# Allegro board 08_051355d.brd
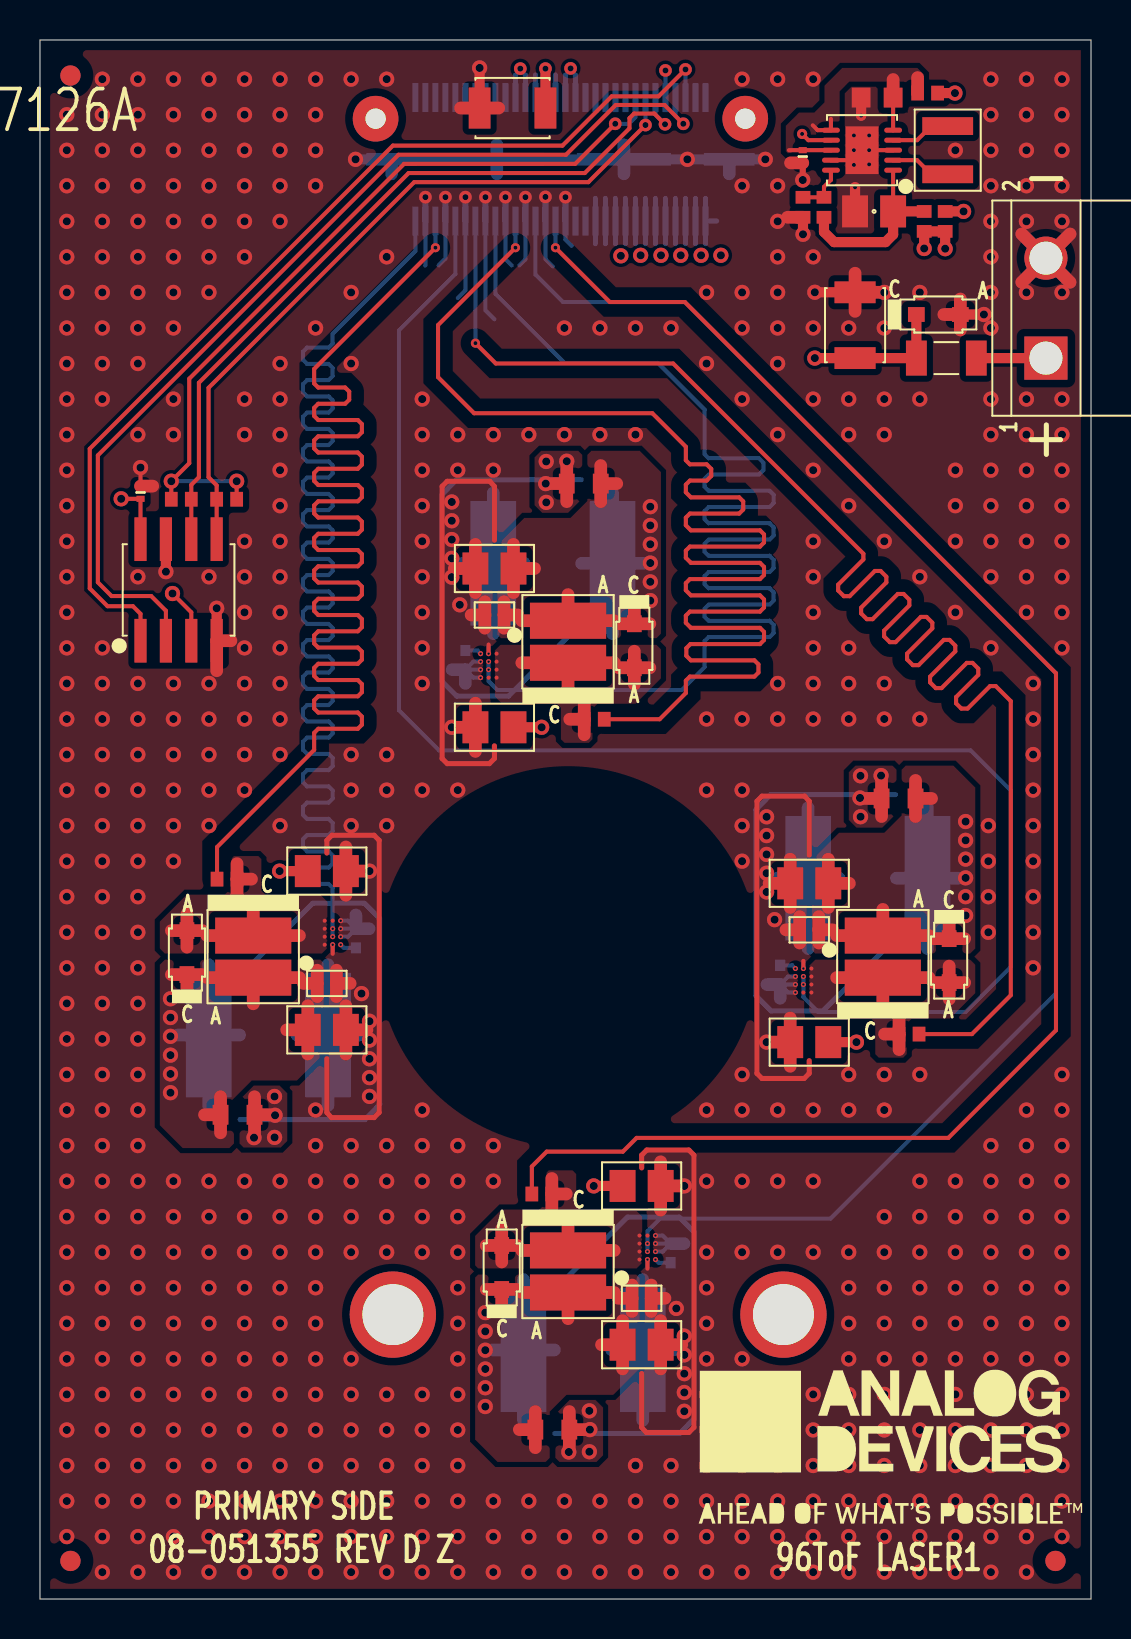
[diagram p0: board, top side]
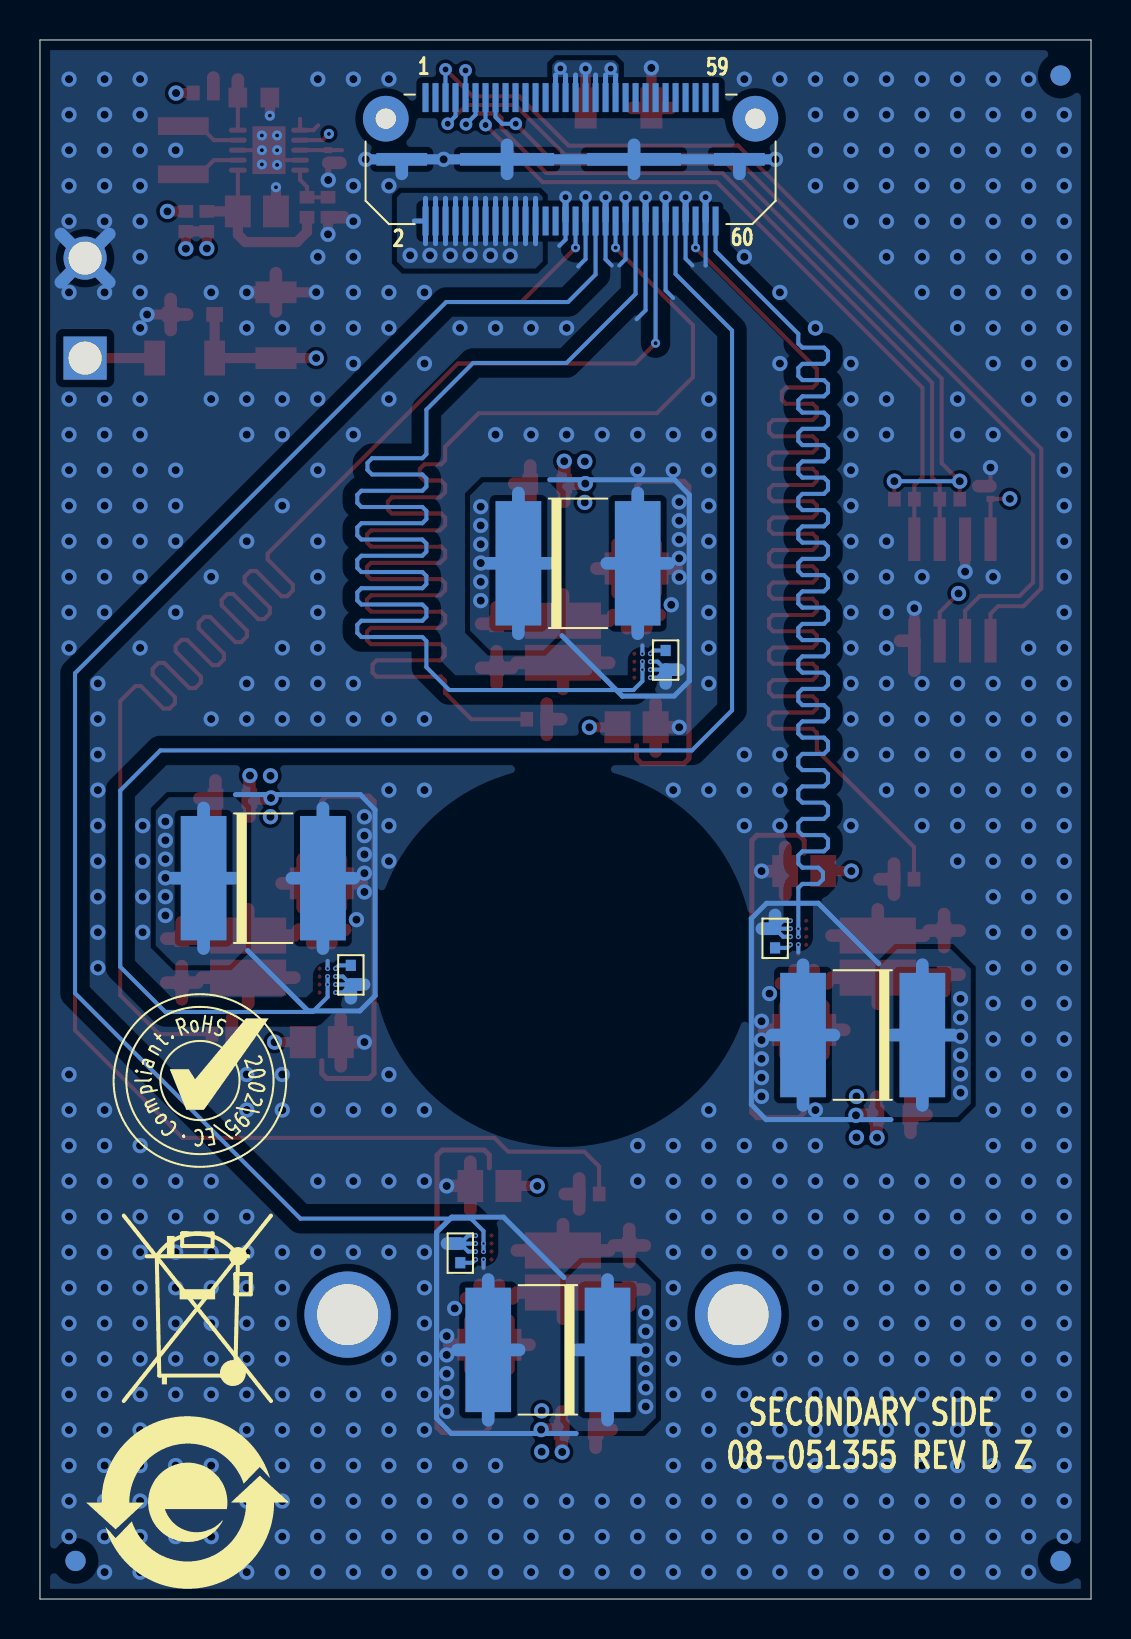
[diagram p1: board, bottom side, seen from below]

Outline 52.58 x 77.98 mm; copper layers: TOP, L2_GND, L3_PWR, L4_PWR, L5_GND, BOTTOM. Coordinates in mm from the lower left corner of the outline.
Outline path: 0,77.98 52.58,77.98 52.58,0 0,0 0,77.98

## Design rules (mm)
constraint set DEFAULT: min track width 0.102
net group TAL: nets TAL1 TAL2 TAL3 TAL4

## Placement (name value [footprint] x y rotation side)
C1  0.1uF  [C0402H22]  15.8 33.05 90 bottom
C2  0.1uF  [C0402H22]  31.55 17.3 90 bottom
C3  4.7UF  [C0805H53]  14.35 36.41 0 top
C4  4.7UF  [C0805H53]  30.1 20.66 0 top
C5  0.1uF  [C0402H22]  14.35 30.79 0 top
C6  0.1uF  [C0402H22]  38.48 33.47 180 top
C7  0.1uF  [C0402H22]  21.28 46.96 270 bottom
C8  0.1uF  [C0402H22]  37.03 31.21 270 bottom
C9  0.1uF  [C0402H22]  22.73 49.22 180 top
C10  0.1uF  [C0402H22]  30.1 15.04 0 top
C11  4.7UF  [C0805H53]  22.73 43.6 180 top
C12  4.7UF  [C0805H53]  38.48 27.85 180 top
C18  22UF  [C1210H106]  40.77 63.71 270 top
C19  22UF  [C1210H106]  23.64 74.57 0 top
C20  470UF  [C7260]  11.42 28.21 0 bottom
C21  470UF  [C7260]  41.41 36.05 180 bottom
C22  470UF  [C7260]  27.17 12.46 0 bottom
C23  470UF  [C7260]  25.66 51.8 180 bottom
C24  10uF  [C0603]  41.88 75.1 0 top
C25  0.1uF  [C0201]  38.16 72.15 270 top
C26  22UF  [C0805H60]  41.73 69.4 0 top
C27  4.7UF  [C0805H53]  14.35 28.47 0 top
C28  4.7UF  [C0805H53]  38.48 35.8 180 top
C29  4.7UF  [C0805H53]  30.1 12.72 0 top
C30  4.7UF  [C0805H53]  22.73 51.54 180 top
C31  0.1uF  [C0201]  5.03 55.35 270 top
D1  PLZ13B-G3/H  [DO219AC]  7.35 32.33 90 top
D6  PLZ13B-G3/H  [DO219AC]  23.1 16.58 90 top
D8  PLZ13B-G3/H  [DO219AC]  44.94 64.25 0 top
D9  PLZ13B-G3/H  [DO219AC]  29.73 47.68 270 top
D10  PLZ13B-G3/H  [DO219AC]  45.48 31.93 270 top
L1  1.5UH  [L1008_A]  45.41 72.47 270 top
LD1  I940-G2332-NBC-D1-60B45R  [VCSEL2_3_5X3_5]  10.67 32.13 270 top
LD2  I940-G2332-NBC-D1-60B45R  [VCSEL2_3_5X3_5]  42.16 32.13 90 top
LD3  I940-G2332-NBC-D1-60B45R  [VCSEL2_3_5X3_5]  26.42 47.88 90 top
LD4  I940-G2332-NBC-D1-60B45R  [VCSEL2_3_5X3_5]  26.42 16.38 270 top
NOREF  -  []  0 0 0 top
NOREF#2  -  []  206.43 -47.55 0 top
NOREF#3  -  [unnamed#2]  1.52 76.2 0 top
NOREF#4  -  []  201.92 -58.42 0 top
NOREF#5  -  []  10.67 32.13 0 top
NOREF#6  -  []  0 0 0 top
NOREF#7  -  []  26.57 98.68 0 top
NOREF#8  -  [unnamed#2]  37.19 14.22 0 top
NOREF#9  -  []  -170.05 -267.97 0 top
NOREF#10  -  []  26.42 32.13 0 top
NOREF#11  -  []  215.9 215.9 0 top
NOREF#12  -  []  226.11 -117.6 0 top
NOREF#13  -  []  8.51 34.37 0 top
NOREF#14  -  []  52.58 0 90 top
NOREF#15  -  []  0 77.98 0 top
NOREF#16  -  []  26.42 32.13 0 top
NOREF#17  -  []  0 77.98 270 top
NOREF#18  -  []  0 0 0 top
NOREF#19  -  []  19.96 38.24 0 top
NOREF#20  -  []  -34.29 -74.04 0 top
NOREF#21  -  []  -152.4 -254 0 top
NOREF#22  -  [unnamed#2]  50.8 1.91 0 top
NOREF#23  -  []  42.57 7.59 0 top
NOREF#24  -  []  52.58 0 90 top
NOREF#25  -  []  26.42 16.38 90 top
NOREF#26  -  []  119.38 127 0 top
NOREF#27  -  []  0 77.98 0 top
NOREF#28  -  []  1.52 1.91 0 top
NOREF#29  -  []  52.58 0 0 top
NOREF#30  -  []  52.7 77.98 180 top
NOREF#31  -  [unnamed#2]  1.52 1.91 0 top
NOREF#32  -  []  1.52 1.91 0 top
NOREF#33  -  [unnamed#2]  17.65 14.22 0 top
NOREF#34  -  [unnamed#2]  50.8 1.91 180 bottom
NOREF#35  -  [unnamed#2]  1.52 1.91 180 bottom
NOREF#36  -  [unnamed#2]  1.52 76.2 180 bottom
NOREF#37  -  []  35.43 22.86 180 bottom
NOREF#38  -  []  44.58 25.93 180 bottom
NOREF#39  -  []  45.19 4.83 180 bottom
P1  QTH-030-03-L-D-A  [CNSAMTECQTH-030-03-X-D-A]  26.04 72.01 180 bottom
P2  Z5.530.3225.0  [CNWIELAND3225]  50.32 62.07 90 top
R3  50  [R0402]  27.73 44 0 top
R5  0  [R0603]  9.88 24.22 180 top
R6  0  [R0603]  25.63 8.47 180 top
R11  0  [R0603]  27.2 55.79 0 top
R13  0  [R0603]  42.95 40.04 0 top
R22  0  [R1206]  45.34 62.07 0 top
R25  50  [R0402]  9.36 36.01 180 top
R26  50  [R0402]  43.47 28.26 0 top
R29  50  [R0402]  25.11 20.26 180 top
R35  0  [R0402]  38.17 69.61 90 top
R36  0  [R0402]  44.4 75.32 0 top
R37  0  [R0402]  39.22 69.61 270 top
R38  0  [R0402]  45.28 68.9 90 top
R39  0  [R0402]  44.23 68.9 270 top
R40  10K  [R0402]  9.34 55.01 180 top
R41  10K  [R0402]  7.07 55.01 0 top
U1  ADP5202BCBZRL  [WLCSP12H22]  14.64 33.33 0 top
U2  ADP5202BCBZRL  [WLCSP12H22]  38.19 30.94 180 top
U3  ADP5202BCBZRL  [WLCSP12H22]  22.44 46.68 180 top
U4  ADP5202BCBZRL  [WLCSP12H22]  30.39 17.58 0 top
U5  ADP2504ACPZ-5.0  [DFN10_3X3_PAD2_38X1_64]  41.12 72.47 90 top
U6  ADT7410TRZ  [SO8]  6.93 50.47 0 top

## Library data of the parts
C1 C2 C5-C10 = CAP: Tolerance: 10; User Part Number: UPN; alternate symbols: (); part number: CAP_SM-0.1UF,50V,10,E018452,C0402H22; tolerance: 10
C3 C4 C11 C12 C27-C30 = CAP: Tolerance: 10; User Part Number: UPN; alternate symbols: (); part number: CAP_SM-4.7UF,25V,10,E025752,C0805H53; tolerance: 10
C18 C19 = CAP: Tolerance: 10; User Part Number: UPN; alternate symbols: (); part number: CAP_SM-22UF,25V,10,E025745,C1210H106; tolerance: 10
C20-C23 = CAPP: Tolerance: 10; User Part Number: UPN; alternate symbols: (); part number: CAPP_SM-470UF,10V,10,E027243,C7260; tolerance: 10
C24 = CAP: User Part Number: UPN; Tolerance: 20; alternate symbols: (); part number: CAP_SM-10UF,6.3V,20,E007143,C0603; tolerance: 20
C25 C31 = CAP: Tolerance: 20; User Part Number: UPN; alternate symbols: (); part number: CAP_SM-0.1UF,16V,20,E017331,C0201; tolerance: 20
C26 = CAP: Tolerance: 20; User Part Number: UPN; alternate symbols: (); part number: CAP_SM-22UF,10V,20,E032369,C0805H60; tolerance: 20
D1 D6 D8-D10 = DIOZNR: User Part Number: UPN; Tolerance: 2; alternate symbols: (); part number: DIOZNR_SM-PLZ13B-G3/H,13V,2,E025186,DO219AC; tolerance: 2
L1 = IND: Tolerance: 20; User Part Number: UPN; alternate symbols: (); part number: IND_SM-1.5UH,20,E026128,L1008_A; tolerance: 20
LD1-LD4 = DIOLASER: User Part Number: UPN; Tolerance: N/A; alternate symbols: (); part number: DIOLASER_SM-I940-G2332-NBC-D1-110B85R,5V,N/A,E035420,VCSEL2_3_5X3_5; tolerance: N/A
P1 = CN60P_ODD_EVEN_4GND: User Part Number: UPN; Tolerance: N/A; alternate symbols: (); part number: CN60P_ODD_EVEN_4GND_SM-QTH-030-03-L-D-A,E035156,CNSAMTECQTH-030-03-X-D-A; tolerance: N/A
P2 = CN2P: User Part Number: UPN; Tolerance: N/A; alternate symbols: (); part number: CN2P_TH-Z5.530.3225.0,E008161,CNWIELAND3225; tolerance: N/A
R3 R25 R26 R29 = RES: User Part Number: UPN; Tolerance: 0.1; alternate symbols: (R0402L); part number: RES_SM-50,E016309,1/20W,0.1,R0402; tolerance: 0.1
R5 R6 R11 R13 = RES: User Part Number: UPN; Tolerance: 5; alternate symbols: (R0603L); part number: RES_SM-0,E006826,1/10W,5,R0603; tolerance: 5
R22 = RES: User Part Number: UPN; Tolerance: N/A; alternate symbols: (); part number: RES_SM-0,E014206,1/2W,N/A,R1206; tolerance: N/A
R35-R39 = RES: User Part Number: UPN; Tolerance: 5; alternate symbols: (R0402L,R0402L_ALT); part number: RES_SM-0,E003438,N/A,5,R0402; tolerance: 5
R40 R41 = RES: User Part Number: UPN; Tolerance: 5; alternate symbols: (R0402L); part number: RES_SM-10K,E017176,1/10W,5,R0402; tolerance: 5
U1-U4 = ADP5202: Tolerance: N/A; User Part Number: UPN; alternate symbols: (); part number: ADP5202_SM-ADP5202BCBZRL,E034392,WLCSP12H22; tolerance: N/A
U5 = ADP250X: Tolerance: N/A; User Part Number: UPN; alternate symbols: (); part number: ADP250X_SM-ADP2504ACPZ-5.0,E033974,DFN10_3X3_PAD2_38X1_64; tolerance: N/A
U6 = ADT7410: Tolerance: N/A; User Part Number: UPN; alternate symbols: (); part number: ADT7410_SM-ADT7410TRZ,E010871,SO8; tolerance: N/A

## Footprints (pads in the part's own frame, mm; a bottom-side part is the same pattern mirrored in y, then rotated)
C0201
  rect 0.305x0.406 smd: 1(-0.318,0) 2(0.318,0)
C0402H22
  rect 0.559x0.508 smd: 1(-0.479,0) 2(0.479,0)
C0603
  rect 0.94x0.991 smd: 1(-0.8,0) 2(0.8,0)
C0805H53
  rect 1.295x1.6 smd: 1(-0.953,0) 2(0.953,0)
C0805H60
  rect 1.295x1.6 smd: 1(-0.953,0) 2(0.953,0)
C1210H106
  rect 1.092x2.057 smd: 1(-1.646,0) 2(1.646,0)
C7260
  rect 2.286x6.223 smd: N(2.985,0) P(-2.985,0)
CNSAMTECQTH-030-03-X-D-A
  round 2.286 hole 1.016 unplated: (-9.246,2.032) (9.246,2.032)
  rect 0.305x1.448 smd: 1(-7.257,3.086) 2(-7.257,-3.086) 3(-6.756,3.086) 4(-6.756,-3.086) 5(-6.256,3.086) 6(-6.256,-3.086) 7(-5.756,3.086) 8(-5.756,-3.086) 9(-5.255,3.086) 10(-5.255,-3.086) 11(-4.755,3.086) 12(-4.755,-3.086) 13(-4.255,3.086) 14(-4.255,-3.086) 15(-3.754,3.086) 16(-3.754,-3.086) 17(-3.254,3.086) 18(-3.254,-3.086) 19(-2.753,3.086) 20(-2.753,-3.086) 21(-2.253,3.086) 22(-2.253,-3.086) 23(-1.753,3.086) 24(-1.753,-3.086) 25(-1.252,3.086) 26(-1.252,-3.086) 27(-0.752,3.086) 28(-0.752,-3.086) 29(-0.251,3.086) 30(-0.251,-3.086) 31(0.249,3.086) 32(0.249,-3.086) 33(0.749,3.086) 34(0.749,-3.086) 35(1.25,3.086) 36(1.25,-3.086) 37(1.75,3.086) 38(1.75,-3.086) 39(2.25,3.086) 40(2.25,-3.086) 41(2.751,3.086) 42(2.751,-3.086) 43(3.251,3.086) 44(3.251,-3.086) 45(3.752,3.086) 46(3.752,-3.086) 47(4.252,3.086) 48(4.252,-3.086) 49(4.752,3.086) 50(4.752,-3.086) 51(5.253,3.086) 52(5.253,-3.086) 53(5.753,3.086) 54(5.753,-3.086) 55(6.253,3.086) 56(6.253,-3.086) 57(6.754,3.086) 58(6.754,-3.086) 59(7.254,3.086) 60(7.254,-3.086)
  rect 2.54x0.635 smd: PAD1(-8.445,0) PAD4(8.445,0)
  rect 4.699x0.635 smd: PAD2(-3.175,0) PAD3(3.175,0)
CNWIELAND3225
  rect 2.159x2.159 hole 1.651: 1(0,0)
  round 2.159 hole 1.651: 2(5,0)
DFN10_3X3_PAD2_38X1_64
  oval 0.254x0.889 smd: 1(-1,-1.555) 2(-0.5,-1.555) 3(0,-1.555) 4(0.5,-1.555) 5(1,-1.555) 6(1,1.555) 7(0.5,1.555) 8(0,1.555) 9(-0.5,1.555) 10(-1,1.555)
  rect 2.388x1.651 smd: PAD(0,0)
DO219AC
  rect 0.838x0.737 smd: A(1.1,0) C(-1.1,0)
L1008_A
  rect 0.889x2.54 smd: 1(-1.206,0) 2(1.206,0)
R0402
  rect 0.635x0.737 smd: 1(-0.5,0) 2(0.5,0)
R0603
  rect 0.787x0.991 smd: 1(-0.85,0) 2(0.85,0)
R1206
  rect 1.041x1.753 smd: 1(-1.5,0) 2(1.5,0)
SO8
  rect 0.61x2.184 smd: 1(-1.905,-2.54) 2(-0.635,-2.54) 3(0.635,-2.54) 4(1.905,-2.54) 5(1.905,2.54) 6(0.635,2.54) 7(-0.635,2.54) 8(-1.905,2.54)
unnamed#2
  round 1.016 smd: (0,0)
VCSEL2_3_5X3_5
  rect 1.803x3.81 smd: A(1.052,0) C(-1.052,0)
WLCSP12H22
  round 0.203 smd: A1(-0.4,-0.6) A2(-0.4,-0.2) A3(-0.4,0.2) A4(-0.4,0.6) B1(0,-0.6) B2(0,-0.2) B3(0,0.2) B4(0,0.6) C1(0.4,-0.6) C2(0.4,-0.2) C3(0.4,0.2) C4(0.4,0.6)

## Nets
5V_LD: C1.1 C2.1 C3.1 C4.1 C7.1 C8.1 C11.1 C12.1 R38.1 R39.2(N2) U1.C1(VS) U2.C1(VS) U3.C1(VS) U4.C1(VS)
5VDD_CON: C19.2(N2) P1.27 P1.29 P1.31 P1.33 P1.35 P1.37 P1.39 R36.2(N2) R38.2(N2) U5.7
AGND: C1.2(N2) C2.2(N2) C3.2(N2) C4.2(N2) C5.2(N2) C6.2(N2) C7.2(N2) C8.2(N2) C9.2(N2) C10.2(N2) C11.2(N2) C12.2(N2) C18.1 C19.1 C20.N(N2) C21.N(N2) C22.N(N2) C23.N(N2) C24.1 C25.2(N2) C26.1 C27.2(N2) C28.2(N2) C29.2(N2) C30.2(N2) C31.1 D8.A(P) P1.30 P1.34 P1.38 P1.42 P1.46 P1.50 P1.54 P1.58 P1.PAD1 P1.PAD2 P1.PAD3 P1.PAD4 P2.2(N2) R35.1 U1.B1 U1.C2 U1.C3 U1.C4 U2.B1 U2.C2 U2.C3 U2.C4 U3.B1 U3.C2 U3.C3 U3.C4 U4.B1 U4.C2 U4.C3 U4.C4 U5.3 U5.9 U5.PAD U6.4 U6.7
VIN: C24.2(N2) C25.1 R36.1 U5.5 U5.6 U5.8
3P3VDD: C31.2(N2) P1.9 U6.3 U6.8(VDD)
CATHODE1: D1.A(P) LD1.C R25.1 U1.A1 U1.A2 U1.A3 U1.A4
CATHODE2: D10.A(P) LD2.C R26.1 U2.A1 U2.A2 U2.A3 U2.A4
CATHODE3: D9.A(P) LD3.C R3.1 U3.A1 U3.A2 U3.A3 U3.A4
CATHODE4: D6.A(P) LD4.C R29.1 U4.A1 U4.A2 U4.A3 U4.A4
CT_LASER: P1.11 R41.2(N2) U6.6
DS1: C5.1 C20.P C27.1 D1.C LD1.A R5.2(N2)
DS2: C6.1 C21.P C28.1 D10.C LD2.A R13.2(N2)
DS3: C9.1 C23.P C30.1 D9.C LD3.A R11.2(N2)
DS4: C10.1 C22.P C29.1 D6.C LD4.A R6.2(N2)
I2C0_SCL: P1.5 U6.1
I2C0_SDA: P1.7 U6.2
INT_LASER: P1.13 R40.2(N2) U6.5
IOVDD: P1.15 R40.1 R41.1
LD1: P1.60 U1.B2 U1.B3
LD2: P1.52 U2.B2 U2.B3
LD3: P1.44 U3.B2 U3.B3
LD4: P1.36 U4.B2 U4.B3
LD_SUPPLY: P2.1 R5.1 R6.1 R11.1 R13.1 R22.2(N2)
TAL1: P1.56 R25.2(N2)
TAL2: P1.48 R26.2(N2)
TAL3: P1.40 R3.2(N2)
TAL4: P1.32 R29.2(N2)
UNNAMED_4_ADP250X_I213_FB: R35.2(N2) R37.1 U5.10
UNNAMED_4_ADP250X_I213_SW1: L1.1 U5.4
UNNAMED_4_ADP250X_I213_SW2: L1.2(N2) U5.2
VLD_BRD: C18.2(N2) D8.C P1.2 P1.4 P1.6 P1.8 P1.10 P1.12 P1.14 P1.16 P1.18(N9) P1.20 P1.22 P1.24 R22.1
VOUT: C26.2(N2) R37.2(N2) R39.1 U5.1(VOUT)

Pads without a net: P1 1 3 17 19 21 23 25 26 28 41 43 45 47 49 51 53 55 57 59; U1 B4; U2 B4; U3 B4; U4 B4

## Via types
v1: diameter 0.762, hole 0.406, TOP to BOTTOM, 688 vias
v2: diameter 0.635, hole 0.305, TOP to BOTTOM, 17 vias
v3: diameter 0.254, hole 0.127, TOP to BOTTOM, 28 vias
v4: diameter 0.508, hole 0.203, TOP to BOTTOM, 9 vias
v5: diameter 0.457, hole 0.203, TOP to BOTTOM, 4 vias

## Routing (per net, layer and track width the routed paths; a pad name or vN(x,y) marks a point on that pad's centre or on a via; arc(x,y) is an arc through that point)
5V_LD: length 11.8
  TOP w0.508: v1(44.23,67.55) R39.2 R38.1 v1(45.28,67.54) ; C4.1 v1(27.7,20.66) ; C3.1 v1(11.99,36.41) ; C12.1 v1(40.84,27.85) ; C11.1 v1(25.1,43.6)
  BOTTOM w0.203: C1.1 15.2,32.57 v3(15.04,32.73) ; v3(30.79,16.98) 30.95,16.82 C2.1 ; C8.1 37.63,31.69 v3(37.79,31.54) ; C7.1 21.88,47.44 v3(22.04,47.28)
5VDD_CON: length 13.3
  TOP w0.203: v4(38.13,73.28) 38.44,72.97 U5.7
  TOP w0.508: C19.2 v2(25.29,76.55) ; R38.2 v1(46.2,69.4) ; R36.2 v1(45.77,75.32)
  BOTTOM w0.254: P1.35 24.79,76.23 ; P1.33 25.29,76.23 ; 26.54,76.53 v2(26.54,76.56) ; P1.39 23.78,76.23 ; P1.37 24.28,76.23 ; P1.27 26.79,76.23 ; P1.31 25.79,76.23 ; P1.29 26.29,76.23
  vias: v2(24.03,76.55)
AGND: length 206.1
  TOP w0.203: U5.3 v4(41.48,72.47) ; U5.9 40.48,71.97 v4(40.72,71.73) ; v3(22.44,47.28) 22.44,47.74 ; v3(30.39,16.98) 30.39,16.52 ; v3(14.64,32.73) 14.64,32.27 ; C31.1 v1(5.03,56.59) ; v3(38.19,31.54) 38.19,31.92
  TOP w0.305: C25.2 v1(38.16,70.97)
  TOP w0.508: C26.1 v4(40.77,70.61) ; U6.7 v1(6.3,51.38) ; C24.1 v4(41.08,74.2) ; R35.1 v1(38.17,68.26) ; D8.A v1(47.22,64.25) ; C18.1 v1(38.76,65.36) ; C19.1 v1(21.99,76.58) ; U6.4 v1(8.84,49.56)
  TOP w0.635: 40.77,64.41 C18.1 ; C18.1 40.77,66.31 ; C18.1 42.21,65.36 ; C11.2 21.78,44.81 ; C11.2 20.73,43.6 ; C11.2 21.78,42.39 ; 21.78,50.34 C30.2 ; C30.2 20.73,51.54 ; C30.2 21.78,52.75 ; C9.2 22.25,49.88 ; C9.2 21.57,49.22 ; C9.2 22.25,48.56 ; C10.2 30.58,15.7 ; C10.2 30.58,14.38 ; C10.2 31.26,15.04 ; 46.04,63.47 D8.A ; D8.A 45.22,64.25 ; D8.A 46.04,65.02 ; C3.2 16.36,36.41 ; C3.2 15.3,37.62 ; C3.2 15.3,35.2 ; 37.55,71.83 C25.2 ; 36.48,35.8 C28.2 ; C28.2 37.53,37 ; C28.2 37.53,34.59 ; P2.2 51.53,65.86 ; P2.2 49.12,65.86 ; P2.2 51.53,68.27 ; P2.2 49.12,68.27 ; C6.2 38,34.13 ; C6.2 38,32.81 ; C6.2 37.32,33.47 ; 8.84,46.43 U6.4 9.55,47.93 ; C5.2 14.83,31.45 ; C5.2 15.52,30.79 ; C5.2 14.83,30.13 ; C4.2 32.1,20.66 ; C4.2 31.05,21.87 ; C4.2 31.05,19.45 ; C31.1 5.64,55.66 ; C27.2 15.3,29.67 ; C27.2 16.36,28.47 ; C27.2 15.3,27.26 ; 37.53,26.65 C12.2 ; C12.2 37.53,29.06 ; C12.2 36.48,27.85 ; 31.05,11.51 C29.2 ; C29.2 32.1,12.72 ; C29.2 31.05,13.92 ; 37.39,69.11 R35.1 ; 21.04,74.57 C19.1 22.95,74.57
  L2_GND w0.635: 49.12,65.86 P2.2 ; P2.2 49.12,68.27 ; P2.2 51.53,68.27 ; P2.2 51.53,65.86
  L5_GND w0.635: 49.12,68.27 P2.2 ; P2.2 51.53,68.27 ; P2.2 49.12,65.86 ; P2.2 51.53,65.86
  BOTTOM w0.203: v3(37.79,30.34) 37.43,30.34 C8.2 ; 25.65,66.65 25.29,67.02 P1.34 ; C7.2 21.68,46.08 v3(22.04,46.08) ; C7.2 v3(22.04,46.48) ; C7.2 21.68,46.88 v3(22.04,46.88) ; P1.42 23.28,67.01 23.6,66.7 ; C2.2 31.15,18.18 v3(30.79,18.18) ; C2.2 v3(30.79,17.78) ; C2.2 31.15,17.38 v3(30.79,17.38) ; C8.2 v3(37.79,30.74) ; C8.2 37.43,31.14 v3(37.79,31.14) ; P1.50 21.28,65.45 20.9,65.07 ; v3(15.04,33.93) 15.4,33.93 C1.2 ; 23.98,66.7 24.28,67.01 P1.38 ; 19.94,66.7 20.28,67.04 P1.54 ; 19.28,66.7 19.28,66.7 P1.58 ; v3(14.64,32.73) 14.64,32.35 ; v3(15.04,33.53) C1.2 ; C1.2 15.4,33.13 v3(15.04,33.13) ; v3(38.19,31.54) 38.19,31.91 ; v3(30.39,16.98) 30.39,16.57 ; P1.30 26.29,68 26.59,67.69 26.59,67.69 ; v3(22.44,47.28) 22.44,47.69 ; P1.46 22.28,64.46 22.73,64.01
  BOTTOM w0.305: v2(22.28,70.12) P1.46 ; v2(26.29,70.12) P1.30 ; P1.38 v2(24.28,70.12) ; P1.34 v2(25.29,70.13) ; P1.58 v2(19.28,70.12) ; P1.42 v2(23.28,70.12) ; P1.54 v2(20.28,70.12) ; P1.50 v2(21.28,70.12)
  BOTTOM w0.508: v1(15.79,72.01) P1.PAD4 P1.PAD3 P1.PAD2 v1(32.38,72.01) P1.PAD1 v1(36.28,72.01)
  BOTTOM w0.635: 21.28,45.8 C7.2 20.62,46.48 ; 49.12,65.86 P2.2 ; P2.2 49.12,68.27 ; P2.2 51.53,65.86 ; P2.2 51.53,68.27 ; 22.86,72.73 P1.PAD3 22.86,71.29 ; 29.21,71.29 P1.PAD2 29.21,72.73 ; C22.N 30.16,15.98 ; C22.N 31.7,12.46 ; C22.N 30.16,8.94 ; C22.N 28.61,12.46 ; C20.N 15.96,28.21 ; C20.N 14.41,31.73 ; C20.N 14.41,24.69 ; C20.N 12.86,28.21 ; C21.N 39.97,36.05 ; C21.N 38.42,32.54 ; C21.N 36.88,36.05 ; C21.N 38.42,39.57 ; 37.03,30.05 C8.2 36.37,30.74 ; 15.8,34.21 C1.2 16.46,33.53 ; C2.2 32.21,17.78 ; C23.N 22.68,55.32 ; C23.N 22.68,48.28 ; C23.N 24.23,51.8 ; C23.N 21.13,51.8 ; 34.48,71.29 P1.PAD1 ; 17.59,71.29 P1.PAD4
  vias: v1(1.34,74.24) v1(1.34,72.46) v1(1.34,70.69) v1(1.34,68.91) v1(1.34,67.13) v1(1.34,65.35) v1(1.34,63.57) v1(1.34,61.8) v1(1.34,60.02) v1(1.34,58.24) v1(1.34,56.46) v1(1.34,54.68) v1(1.34,52.91) v1(1.34,51.13) v1(1.34,49.35) v1(1.34,47.57) v1(1.34,45.79) v1(1.34,44.02) v1(1.34,42.24) v1(1.34,40.46) v1(1.34,38.68) v1(1.34,36.9) v1(1.34,35.13) v1(1.34,33.35) v1(1.34,31.57) v1(1.34,29.79) v1(1.34,28.01) v1(1.34,26.24) v1(1.34,24.46) v1(1.34,22.68) v1(1.34,20.9) v1(1.34,19.12) v1(1.34,17.35) v1(1.34,15.57) v1(1.34,13.79) v1(1.34,12.01) v1(1.34,10.23) v1(1.34,8.46) v1(1.34,6.68) v1(1.34,4.9) v1(1.34,3.12) v1(3.12,76.02) v1(3.12,74.24) v1(3.12,72.46) v1(3.12,70.69) v1(3.12,68.91) v1(3.12,67.13) v1(3.12,65.35) v1(3.12,63.57) v1(3.12,61.8) v1(3.12,60.02) v1(3.12,47.57) v1(3.12,45.79) v1(3.12,44.02) v1(3.12,42.24) v1(3.12,40.46) v1(3.12,38.68) v1(3.12,36.9) v1(3.12,35.13) v1(3.12,33.35) v1(3.12,31.57) v1(3.12,29.79) v1(3.12,28.01) v1(3.12,26.24) v1(3.12,24.46) v1(3.12,22.68) v1(3.12,20.9) v1(3.12,19.12) v1(3.12,17.35) v1(3.12,15.57) v1(3.12,13.79) v1(3.12,12.01) v1(3.12,10.23) v1(3.12,8.46) v1(3.12,6.68) v1(3.12,4.9) v1(3.12,3.12) v1(3.12,1.34) v1(4.9,76.02) v1(4.9,74.24) v1(4.9,72.46) v1(4.9,70.69) v1(4.9,68.91) v1(4.9,67.13) v1(4.9,65.35) v1(4.9,63.57) v1(4.9,61.8) v1(4.9,58.24) v1(4.9,51.13) v1(4.9,45.79) v1(4.9,44.02) v1(4.9,42.24) v1(4.9,40.46) v1(4.9,38.68) v1(4.9,36.9) v1(4.9,35.13) v1(4.9,33.35) v1(4.9,31.57) v1(4.9,29.79) v1(4.9,28.01) v1(4.9,26.24) v1(4.9,24.46) v1(4.9,22.68) v1(4.9,20.9) v1(4.9,19.12) v1(4.9,17.35) v1(4.9,15.57) v1(4.9,13.79) v1(4.9,12.01) v1(4.9,10.23) v1(4.9,8.46) v1(4.9,6.68) v1(4.9,4.9) v1(4.9,3.12) v1(4.9,1.34) v1(6.68,76.02) v1(6.68,74.24) v1(6.68,72.46) v1(6.68,70.69) v1(6.68,68.91) v1(6.68,67.13) v1(6.68,65.35) v1(6.68,63.57) v1(6.68,60.02) v1(6.68,58.24) v1(6.68,45.79) v1(6.68,44.02) v1(6.68,42.24) v1(6.68,40.46) v1(6.68,38.68) v1(6.68,36.9) v1(6.68,20.9) v1(6.68,19.12) v1(6.68,17.35) v1(6.68,15.57) v1(6.68,13.79) v1(6.68,12.01) v1(6.68,10.23) v1(6.68,8.46) v1(6.68,6.68) v1(6.68,4.9) v1(6.68,3.12) v1(6.68,1.34) v1(8.45,76.02) v1(8.45,74.24) v1(8.45,72.46) v1(8.45,70.69) v1(8.45,68.91) v1(8.45,67.13) v1(8.45,65.35) v1(8.45,51.13) v1(8.45,45.79) v1(8.45,44.02) v1(8.45,42.24) v1(8.45,40.46) v1(8.45,38.68) v1(8.45,20.9) v1(8.45,19.12) v1(8.45,17.35) v1(8.45,15.57) v1(8.45,13.79) v1(8.45,12.01) v1(8.45,10.23) v1(8.45,8.46) v1(8.45,6.68) v1(8.45,4.9) v1(8.45,3.12) v1(8.45,1.34) v1(10.23,76.02) v1(10.23,74.24) v1(10.23,72.46) v1(10.23,70.69) v1(10.23,68.91) v1(10.23,67.13) v1(10.23,60.02) v1(10.23,58.24) v1(10.23,52.91) v1(10.23,51.13) v1(10.23,49.35) v1(10.23,47.57) v1(10.23,45.79) v1(10.23,44.02) v1(10.23,42.24) v1(10.23,40.46) v1(10.23,20.9) v1(10.23,19.12) v1(10.23,17.35) v1(10.23,15.57) v1(10.23,13.79) v1(10.23,12.01) v1(10.23,10.23) v1(10.23,8.46) v1(10.23,6.68) v1(10.23,4.9) v1(10.23,3.12) v1(10.23,1.34) v1(12.01,76.02) v1(12.01,74.24) v1(12.01,72.46) v1(12.01,70.69) v1(12.01,68.91) v1(12.01,61.8) v1(12.01,60.02) v1(12.01,58.24) v1(12.01,56.46) v1(12.01,54.68) v1(12.01,52.91) v1(12.01,51.13) v1(12.01,49.35) v1(12.01,47.57) v1(12.01,45.79) v1(12.01,44.02) v1(12.01,42.24) v1(12.01,38.68) v1(12.01,20.9) v1(12.01,19.12) v1(12.01,17.35) v1(12.01,15.57) v1(12.01,13.79) v1(12.01,12.01) v1(12.01,10.23) v1(12.01,8.46) v1(12.01,6.68) v1(12.01,4.9) v1(12.01,3.12) v1(12.01,1.34) v1(13.79,76.02) v1(13.79,74.24) v1(13.79,72.46) v1(13.79,70.69) v1(13.79,63.57) v1(13.79,24.46) v1(13.79,22.68) v1(13.79,20.9) v1(13.79,19.12) v1(13.79,17.35) v1(13.79,15.57) v1(13.79,13.79) v1(13.79,12.01) v1(13.79,10.23) v1(13.79,8.46) v1(13.79,6.68) v1(13.79,4.9) v1(13.79,3.12) v1(13.79,1.34) v1(15.57,76.02) v1(15.57,65.35) v1(15.57,61.8) v1(15.57,42.24) v1(15.57,40.46) v1(15.57,38.68) v1(15.57,22.68) v1(15.57,20.9) v1(15.57,19.12) v1(15.57,17.35) v1(15.57,12.01) v1(15.57,10.23) v1(15.57,8.46) v1(15.57,6.68) v1(15.57,4.9) v1(15.57,3.12) v1(15.57,1.34) v1(16.08,30.28) v1(16.48,36.41) v1(16.48,28.9) v1(16.48,27.96) v1(16.48,27.02) v1(16.48,26.08) v1(16.48,25.14) v1(17.34,76.02) v1(17.34,67.13) v1(17.34,42.24) v1(17.34,40.46) v1(17.34,38.68) v1(17.34,22.68) v1(17.34,20.9) v1(17.34,19.12) v1(17.34,17.35) v1(17.34,10.23) v1(17.34,8.46) v1(17.34,6.68) v1(17.34,4.9) v1(17.34,3.12) v1(17.34,1.34) v1(19.12,60.02) v1(19.12,58.24) v1(19.12,56.46) v1(19.12,54.68) v1(19.12,52.91) v1(19.12,51.13) v1(19.12,49.35) v1(19.12,47.57) v1(19.12,45.79) v1(19.12,40.46) v1(19.12,24.46) v1(19.12,22.68) v1(19.12,20.9) v1(19.12,19.12) v1(19.12,17.35) v1(19.12,10.23) v1(19.12,8.46) v1(19.12,6.68) v1(19.12,4.9) v1(19.12,3.12) v1(19.12,1.34) v1(20.6,54.87) v1(20.6,53.93) v1(20.6,52.99) v1(20.6,52.05) v1(20.6,51.11) v1(20.6,43.6) v1(20.9,58.24) v1(20.9,56.46) v1(20.9,40.46) v1(20.9,22.68) v1(20.9,20.9) v1(20.9,19.12) v1(20.9,17.35) v1(20.9,15.57) v1(20.9,13.79) v1(20.9,12.01) v1(20.9,10.23) v1(20.9,8.46) v1(20.9,6.68) v1(20.9,4.9) v1(20.9,3.12) v1(20.9,1.34) v1(21,49.73) v1(22.68,58.24) v1(22.68,56.46) v1(22.68,22.68) v1(22.68,20.9) v1(22.68,4.9) v1(22.68,3.12) v1(22.68,1.34) v1(24.46,58.24) v1(24.46,4.9) v1(24.46,3.12) v1(24.46,1.34) v1(26.23,63.57) v1(26.23,58.24) v1(26.23,4.9) v1(26.23,3.12) v1(26.23,1.34) v1(28.01,63.57) v1(28.01,58.24) v1(28.01,4.9) v1(28.01,3.12) v1(28.01,1.34) v1(29.79,63.57) v1(29.79,58.24) v1(29.79,6.68) v1(29.79,4.9) v1(29.79,3.12) v1(29.79,1.34) v1(31.57,63.57) v1(31.57,6.68) v1(31.57,4.9) v1(31.57,3.12) v1(31.57,1.34) v1(31.83,14.53) v1(32.23,20.66) v1(32.23,13.15) v1(32.23,12.21) v1(32.23,11.27) v1(32.23,10.33) v1(32.23,9.39) v1(33.35,65.35) v1(33.35,61.8) v1(33.35,44.02) v1(33.35,40.46) v1(33.35,24.46) v1(33.35,20.9) v1(33.35,17.35) v1(33.35,15.57) v1(33.35,13.79) v1(33.35,12.01) v1(33.35,10.23) v1(33.35,8.46) v1(33.35,6.68) v1(33.35,4.9) v1(33.35,3.12) v1(33.35,1.34) v1(35.12,76.02) v1(35.12,70.69) v1(35.12,65.35) v1(35.12,63.57) v1(35.12,60.02) v1(35.12,44.02) v1(35.12,40.46) v1(35.12,38.68) v1(35.12,36.9) v1(35.12,26.24) v1(35.12,24.46) v1(35.12,20.9) v1(35.12,17.35) v1(35.12,12.01) v1(35.12,10.23) v1(35.12,8.46) v1(35.12,6.68) v1(35.12,4.9) v1(35.12,3.12) v1(35.12,1.34) v1(36.35,39.12) v1(36.35,38.18) v1(36.35,37.24) v1(36.35,36.3) v1(36.35,35.36) v1(36.35,27.85) v1(36.75,33.98) v1(36.9,76.02) v1(36.9,70.69) v1(36.9,68.91) v1(36.9,67.13) v1(36.9,65.35) v1(36.9,63.57) v1(36.9,61.8) v1(36.9,58.24) v1(36.9,45.79) v1(36.9,44.02) v1(36.9,24.46) v1(36.9,20.9) v1(36.9,17.35) v1(36.9,10.23) v1(36.9,8.46) v1(36.9,6.68) v1(36.9,4.9) v1(36.9,3.12) v1(36.9,1.34) v1(38.68,76.02) v1(38.68,67.13) v1(38.68,63.57) v1(38.68,60.02) v1(38.68,56.46) v1(38.68,52.91) v1(38.68,51.13) v1(38.68,49.35) v1(38.68,47.57) v1(38.68,45.79) v1(38.68,44.02) v1(38.68,24.46) v1(38.68,20.9) v1(38.68,17.35) v1(38.68,10.23) v1(38.68,8.46) v1(38.68,6.68) v1(38.68,4.9) v1(38.68,3.12) v1(38.68,1.34) v1(40.46,63.57) v1(40.46,60.02) v1(40.46,58.24) v1(40.46,54.68) v1(40.46,47.57) v1(40.46,45.79) v1(40.46,44.02) v1(40.46,26.24) v1(40.46,24.46) v1(40.46,17.35) v1(40.46,15.57) v1(40.46,13.79) v1(40.46,12.01) v1(40.46,10.23) v1(40.46,8.46) v1(40.46,6.68) v1(40.46,4.9) v1(40.46,3.12) v1(40.46,1.34) v1(42.24,65.35) v1(42.24,63.57) v1(42.24,60.02) v1(42.24,58.24) v1(42.24,52.91) v1(42.24,45.79) v1(42.24,44.02) v1(42.24,26.24) v1(42.24,24.46) v1(42.24,19.12) v1(42.24,17.35) v1(42.24,15.57) v1(42.24,13.79) v1(42.24,12.01) v1(42.24,10.23) v1(42.24,8.46) v1(42.24,6.68) v1(42.24,4.9) v1(42.24,3.12) v1(42.24,1.34) v1(44.01,65.35) v1(44.01,60.02) v1(44.01,51.13) v1(44.01,44.02) v1(44.01,26.24) v1(44.01,20.9) v1(44.01,19.12) v1(44.01,17.35) v1(44.01,15.57) v1(44.01,13.79) v1(44.01,12.01) v1(44.01,10.23) v1(44.01,8.46) v1(44.01,6.68) v1(44.01,4.9) v1(44.01,3.12) v1(44.01,1.34) v1(45.79,72.46) v1(45.79,56.46) v1(45.79,54.68) v1(45.79,52.91) v1(45.79,49.35) v1(45.79,20.9) v1(45.79,19.12) v1(45.79,17.35) v1(45.79,15.57) v1(45.79,13.79) v1(45.79,12.01) v1(45.79,10.23) v1(45.79,8.46) v1(45.79,6.68) v1(45.79,4.9) v1(45.79,3.12) v1(45.79,1.34) v1(47.44,38.68) v1(47.44,36.9) v1(47.44,35.13) v1(47.44,33.35) v1(47.57,76.02) v1(47.57,74.24) v1(47.57,72.46) v1(47.57,70.69) v1(47.57,68.91) v1(47.57,67.13) v1(47.57,65.35) v1(47.57,63.57) v1(47.57,60.02) v1(47.57,58.24) v1(47.57,56.46) v1(47.57,54.68) v1(47.57,52.91) v1(47.57,51.13) v1(47.57,47.57) v1(47.57,22.68) v1(47.57,20.9) v1(47.57,19.12) v1(47.57,17.35) v1(47.57,15.57) v1(47.57,13.79) v1(47.57,12.01) v1(47.57,10.23) v1(47.57,8.46) v1(47.57,6.68) v1(47.57,4.9) v1(47.57,3.12) v1(47.57,1.34) v1(49.35,76.02) v1(49.35,74.24) v1(49.35,72.46) v1(49.35,70.69) v1(49.35,68.91) v1(49.35,65.35) v1(49.35,60.02) v1(49.35,58.24) v1(49.35,56.46) v1(49.35,54.68) v1(49.35,52.91) v1(49.35,51.13) v1(49.35,49.35) v1(49.35,24.46) v1(49.35,22.68) v1(49.35,20.9) v1(49.35,19.12) v1(49.35,17.35) v1(49.35,15.57) v1(49.35,13.79) v1(49.35,12.01) v1(49.35,10.23) v1(49.35,8.46) v1(49.35,6.68) v1(49.35,4.9) v1(49.35,3.12) v1(49.35,1.34) v1(49.68,45.79) v1(49.68,44.02) v1(49.68,42.24) v1(49.68,40.46) v1(49.68,38.68) v1(49.68,36.9) v1(49.68,35.13) v1(49.68,33.35) v1(49.68,31.57) v1(51.13,76.02) v1(51.13,74.24) v1(51.13,72.46) v1(51.13,70.69) v1(51.13,68.91) v1(51.13,65.35) v1(51.13,60.02) v1(51.13,58.24) v1(51.13,56.46) v1(51.13,54.68) v1(51.13,52.91) v1(51.13,51.13) v1(51.13,49.35) v1(51.13,47.57) v1(51.13,26.24) v1(51.13,24.46) v1(51.13,22.68) v1(51.13,20.9) v1(51.13,19.12) v1(51.13,17.35) v1(51.13,15.57) v1(51.13,13.79) v1(51.13,12.01) v1(51.13,10.23) v1(51.13,8.46) v1(51.13,6.68) v1(51.13,4.9) v1(51.13,3.12) v4(40.72,73.2) v4(40.72,72.47) v4(41.48,73.2) v4(41.48,71.75)
VIN: length 7
  TOP w0.203: 38.66,73.71 38.9,73.47 U5.6 39.57,74.03 ; C24.2 U5.5 ; U5.8 C25.1 37.47,72.47
  TOP w0.635: R36.1 43.9,76.1 ; C24.2 42.68,76
3P3VDD: length 7.1
  TOP w0.203: v1(6.63,50.29) 7.57,49.35 U6.3 ; U6.8 C31.2 v1(4.06,55.03)
  BOTTOM w0.203: P1.9 v2(31.29,76.45)
CATHODE1: length 11.4
  TOP w0.635: R25.1 9.86,36.78 ; R25.1 10.58,36.01 ; R25.1 9.86,35.23 ; 6.58,33.43 D1.A ; D1.A 7.35,32.61 ; D1.A 7.35,34.26 ; D1.A 8.13,33.43 ; LD1.C 12.98,33.18 ; LD1.C 8.36,33.18 ; LD1.C 10.67,34.49
CATHODE2: length 11.4
  TOP w0.635: 42.16,29.77 LD2.C ; LD2.C 44.48,31.08 ; LD2.C 39.85,31.08 ; 44.71,30.83 D10.A ; D10.A 45.48,30 ; D10.A 45.48,31.66 ; D10.A 46.26,30.83 ; R26.1 42.97,29.03 ; R26.1 42.25,28.26 ; R26.1 42.97,27.48
CATHODE3: length 11.4
  TOP w0.635: LD3.C 28.73,46.83 ; LD3.C 26.42,45.52 ; LD3.C 24.1,46.83 ; R3.1 27.23,44.78 ; R3.1 26.5,44 ; R3.1 27.23,43.23 ; 29.73,45.75 D9.A ; D9.A 30.51,46.58 ; D9.A 28.96,46.58 ; D9.A 29.73,47.4
CATHODE4: length 11.4
  TOP w0.635: 25.61,19.48 R29.1 ; R29.1 26.33,20.26 ; R29.1 25.61,21.03 ; LD4.C 28.73,17.43 ; LD4.C 24.1,17.43 ; LD4.C 26.42,18.74 ; 22.32,17.68 D6.A ; D6.A 23.1,18.51 ; D6.A 23.1,16.86 ; D6.A 23.87,17.68
CT_LASER: length 38.9
  TOP w0.203: U6.6 R41.2 7.57,55.73 7.95,56.11 7.95,60.83 18.44,71.32 27.25,71.32 29.49,73.56 29.49,74.07 29.72,74.3 30.73,74.3 v2(31.27,73.76)
  BOTTOM w0.203: P1.11 30.79,74.24 v2(31.27,73.76)
DS1: length 26.5
  TOP w0.635: 7.35,30.41 D1.C ; D1.C 6.58,31.23 ; D1.C 8.13,31.23 ; 13.87,30.13 C5.1 ; C5.1 13.18,30.79 ; C5.1 13.87,31.45 ; 10.67,29.77 LD1.A ; LD1.A 12.98,31.08 ; LD1.A 8.36,31.08 ; C27.1 13.4,29.67 ; C27.1 12.34,28.47 ; C27.1 13.4,27.26 ; R5.2 9.03,25.12 ; R5.2 8.23,24.22 ; R5.2 9.03,23.32
  BOTTOM w0.635: 6.89,28.21 C20.P ; C20.P 8.44,31.73 ; C20.P 8.44,24.69 ; C20.P 9.99,28.21
  vias: v1(6.53,30.02) v1(6.53,29.08) v1(6.53,28.14) v1(6.53,27.2) v1(6.53,26.26) v1(6.53,25.32)
DS2: length 26.5
  TOP w0.635: R13.2 44.6,40.04 ; R13.2 43.8,39.14 ; R13.2 43.8,40.94 ; C6.1 38.96,34.13 ; C6.1 38.96,32.81 ; C6.1 39.65,33.47 ; D10.C 46.26,33.03 ; D10.C 45.48,33.86 ; D10.C 44.71,33.03 ; 39.43,34.59 C28.1 ; C28.1 39.43,37 ; C28.1 40.49,35.8 ; 39.85,33.18 LD2.A ; LD2.A 42.16,34.49 ; LD2.A 44.48,33.18
  BOTTOM w0.635: 42.84,36.05 C21.P ; C21.P 44.39,39.57 ; C21.P 45.94,36.05 ; C21.P 44.39,32.54
  vias: v1(46.3,38.89) v1(46.3,37.95) v1(46.3,37.01) v1(46.3,36.07) v1(46.3,35.13) v1(46.3,34.19)
DS3: length 26.5
  TOP w0.635: 23.69,50.34 C30.1 ; C30.1 23.69,52.75 ; C30.1 24.74,51.54 ; 23.21,48.56 C9.1 ; C9.1 23.21,49.88 ; C9.1 23.9,49.22 ; R11.2 28.85,55.79 ; R11.2 28.05,54.89 ; R11.2 28.05,56.69 ; D9.C 30.51,48.78 ; D9.C 29.73,49.6 ; D9.C 28.96,48.78 ; 24.1,48.93 LD3.A ; LD3.A 26.42,50.24 ; LD3.A 28.73,48.93
  BOTTOM w0.635: C23.P 28.65,55.32 ; C23.P 27.1,51.8 ; C23.P 30.19,51.8 ; C23.P 28.65,48.28
  vias: v1(30.53,54.64) v1(30.53,53.7) v1(30.53,52.76) v1(30.53,51.82) v1(30.53,50.88) v1(30.53,49.94)
DS4: length 26.5
  TOP w0.635: 23.1,14.66 D6.C ; D6.C 23.87,15.48 ; D6.C 22.32,15.48 ; 26.42,14.02 LD4.A ; LD4.A 28.73,15.33 ; LD4.A 24.1,15.33 ; 29.62,14.38 C10.1 ; C10.1 28.93,15.04 ; C10.1 29.62,15.7 ; R6.2 24.78,9.37 ; R6.2 24.78,7.57 ; R6.2 23.98,8.47 ; C29.1 29.15,13.92 ; C29.1 29.15,11.51 ; C29.1 28.09,12.72
  BOTTOM w0.635: C22.P 24.19,15.98 ; C22.P 24.19,8.94 ; C22.P 22.64,12.46 ; C22.P 25.74,12.46
  vias: v1(22.28,14.33) v1(22.28,13.39) v1(22.28,12.45) v1(22.28,11.51) v1(22.28,10.57) v1(22.28,9.63)
I2C0_SCL: length 50.5
  TOP w0.203: U6.1 5.03,49.28 4.65,49.66 3.38,49.66 2.49,50.55 2.49,57.53 17.65,72.69 26.14,72.69 28.6,75.16 30.94,75.16 v2(32.29,76.5)
  BOTTOM w0.203: P1.5 v2(32.29,76.5)
I2C0_SDA: length 50.3
  TOP w0.203: U6.2 6.3,49.43 5.56,50.16 3.58,50.16 2.9,50.85 2.9,57.2 17.93,72.24 26.31,72.24 28.8,74.73 31.24,74.73 v2(32.18,73.79)
  BOTTOM w0.203: P1.7 31.79,74.17 32.17,73.79 v2(32.18,73.79)
INT_LASER: length 36.4
  TOP w0.203: U6.5 R40.2 8.84,55.7 8.43,56.11 8.43,60.58 18.72,70.87 27.43,70.87 v2(30.29,73.72)
  BOTTOM w0.203: P1.13 v2(30.29,73.72)
IOVDD: length 39.3
  TOP w0.203: R41.1 6.57,55.91 v1(6.57,55.91) 7.47,56.81 7.47,61.04 18.21,71.78 26.77,71.78 v2(28.78,73.79) ; R40.1 v1(9.84,55.91)
  BOTTOM w0.203: v2(28.78,73.79) 29.45,73.79 29.79,74.12 P1.15 ; v1(6.57,55.91) v1(9.84,55.91)
LD1: length 79.4
  BOTTOM w0.203: P1.60 18.78,67.42 14.64,63.28 14.64,62.79 14.44,62.59 13.36,62.59 13.16,62.39 13.16,61.98 13.36,61.78 14.44,61.78 14.64,61.58 14.64,61.17 14.44,60.97 13.36,60.97 13.16,60.76 13.16,60.36 13.36,60.15 14.44,60.15 14.64,59.95 14.64,59.54 14.44,59.34 13.36,59.34 13.16,59.14 13.16,58.73 13.36,58.53 14.44,58.53 14.64,58.32 14.64,57.92 14.44,57.71 13.36,57.71 13.16,57.51 13.16,57.11 13.36,56.9 14.44,56.9 14.64,56.7 14.64,56.29 14.44,56.09 13.36,56.09 13.16,55.89 13.16,55.48 13.36,55.28 14.44,55.28 14.64,55.07 14.64,54.67 14.44,54.46 13.36,54.46 13.16,54.26 13.16,53.85 13.36,53.65 14.44,53.65 14.64,53.45 14.64,53.04 14.44,52.84 13.36,52.84 13.16,52.63 13.16,52.23 13.36,52.03 14.44,52.03 14.64,51.82 14.64,51.42 14.44,51.21 13.36,51.21 13.16,51.01 13.16,50.6 13.36,50.4 14.44,50.4 14.64,50.2 14.64,49.79 14.44,49.59 13.36,49.59 13.16,49.38 13.16,48.98 13.36,48.77 14.44,48.77 14.64,48.57 14.64,48.16 14.44,47.96 13.36,47.96 13.16,47.76 13.16,47.35 13.36,47.15 14.44,47.15 14.64,46.95 14.64,46.54 14.44,46.34 13.36,46.34 13.16,46.13 13.16,45.73 13.36,45.52 14.44,45.52 14.64,45.32 14.64,44.91 14.44,44.71 13.36,44.71 13.16,44.51 13.16,44.1 13.36,43.9 14.44,43.9 14.64,43.69 14.64,43.29 14.44,43.08 13.36,43.08 13.16,42.88 13.16,42.47 13.36,42.27 14.44,42.27 14.64,42.07 14.64,41.66 14.44,41.46 13.36,41.46 13.16,41.26 13.16,40.85 13.36,40.65 14.44,40.65 14.64,40.44 14.64,40.04 14.44,39.83 13.36,39.83 13.16,39.63 13.16,39.22 13.36,39.02 14.44,39.02 14.64,38.82 14.64,38.41 14.44,38.21 13.36,38.21 13.16,38 13.16,37.6 13.36,37.39 14.44,37.39 14.64,37.19 14.64,36.79 14.44,36.58 13.64,36.58 13.41,36.35 13.41,36 13.64,35.77 14.44,35.77 14.64,35.57 v3(14.64,33.53) v3(14.64,33.13)
LD2: length 79.4
  BOTTOM w0.203: P1.52 20.78,66.27 17.96,63.45 17.96,44.45 19.96,42.44 46.56,42.44 48.56,40.44 48.56,31.62 46.3,29.36 38.94,29.36 38.19,30.11 v3(38.19,30.74) v3(38.19,31.14)
LD3: length 79.4
  BOTTOM w0.203: P1.44 22.78,65.28 26.24,61.82 30.91,61.82 33.25,59.49 33.25,57.26 33.45,57.06 35.97,57.06 36.2,56.83 36.2,56.47 35.97,56.24 33.45,56.24 33.25,56.04 33.25,55.64 33.45,55.43 36.5,55.43 36.7,55.23 36.7,54.82 36.5,54.62 33.45,54.62 33.25,54.42 33.25,54.01 33.45,53.81 36.5,53.81 36.7,53.6 36.7,53.2 36.5,52.99 33.45,52.99 33.25,52.79 33.25,52.38 33.45,52.18 36.5,52.18 36.7,51.98 36.7,51.57 36.5,51.37 33.45,51.37 33.25,51.16 33.25,50.76 33.45,50.56 36.5,50.56 36.7,50.35 36.7,49.95 36.5,49.74 33.45,49.74 33.25,49.54 33.25,49.13 33.45,48.93 36.5,48.93 36.7,48.73 36.7,48.32 36.5,48.12 33.45,48.12 33.25,47.91 33.25,46.61 32.11,45.47 22.89,45.47 22.44,45.91 v3(22.44,46.48) v3(22.44,46.88)
LD4: length 79.4
  BOTTOM w0.203: P1.36 24.79,66.25 26.16,64.87 32.26,64.87 50.83,46.3 50.83,30.3 39.55,19.02 31.01,19.02 30.39,18.4 v3(30.39,17.78) v3(30.39,17.38)
LD_SUPPLY: length 13.9
  TOP w0.508: R22.2 P2.1
  TOP w0.635: R5.1 10.73,25.12 ; R5.1 11.53,24.22 ; R5.1 10.73,23.32 ; R6.1 27.28,8.47 ; R6.1 26.48,7.57 ; R6.1 26.48,9.37 ; R11.1 26.35,56.69 ; R11.1 25.55,55.79 ; R11.1 26.35,54.89 ; R13.1 42.1,40.94 ; R13.1 42.1,39.14 ; R13.1 41.3,40.04
  vias: v1(10.71,23.08) v1(11.73,25.13) v1(11.76,24.2) v1(11.73,23.09) v1(25.32,56.9) v1(25.3,55.79) v1(25.33,54.85) v1(26.35,56.91) v1(26.45,7.35) v1(27.48,9.41) v1(27.51,8.47) v1(27.48,7.37) v1(41.05,41.17) v1(41.02,40.07) v1(41.05,39.13) v1(42.07,41.19)
TAL1: length 83.5
  TOP w0.203: v5(19.78,67.59) 13.72,61.52 13.72,60.8 13.92,60.6 15.27,60.6 15.47,60.39 15.47,59.99 15.27,59.78 13.92,59.78 13.72,59.58 13.72,59.17 13.92,58.97 15.9,58.97 16.1,58.77 16.1,58.36 15.9,58.16 13.92,58.16 13.72,57.95 13.72,57.55 13.92,57.34 15.9,57.34 16.1,57.14 16.1,56.73 15.9,56.53 13.92,56.53 13.72,56.33 13.72,55.92 13.92,55.72 15.9,55.72 16.1,55.52 16.1,55.11 15.9,54.91 13.92,54.91 13.72,54.7 13.72,54.3 13.92,54.09 15.9,54.09 16.1,53.89 16.1,53.48 15.9,53.28 13.92,53.28 13.72,53.08 13.72,52.67 13.92,52.47 15.9,52.47 16.1,52.26 16.1,51.86 15.9,51.65 13.92,51.65 13.72,51.45 13.72,51.04 13.92,50.84 15.9,50.84 16.1,50.64 16.1,50.23 15.9,50.03 13.92,50.03 13.72,49.83 13.72,49.42 13.92,49.22 15.9,49.22 16.1,49.01 16.1,48.61 15.9,48.4 13.92,48.4 13.72,48.2 13.72,47.79 13.92,47.59 15.9,47.59 16.1,47.39 16.1,46.98 15.9,46.78 13.92,46.78 13.72,46.57 13.72,46.17 13.92,45.96 15.9,45.96 16.1,45.76 16.1,45.36 15.9,45.15 13.92,45.15 13.72,44.95 13.72,44.54 13.92,44.34 15.9,44.34 16.1,44.14 16.1,43.73 15.9,43.53 13.92,43.53 13.72,43.32 13.72,42.47 8.86,37.61 R25.2
  BOTTOM w0.203: P1.56 v5(19.78,67.59)
TAL2: length 83.5
  TOP w0.203: v5(21.78,62.81) 22.8,61.8 31.67,61.8 41.19,52.28 41.19,51.99 39.93,50.73 39.93,50.45 40.22,50.16 40.5,50.16 41.76,51.42 42.05,51.42 42.34,51.13 42.34,50.85 41.08,49.58 41.08,49.3 41.36,49.01 41.65,49.01 42.91,50.27 43.2,50.27 43.49,49.98 43.49,49.7 42.23,48.43 42.23,48.15 42.51,47.86 42.8,47.86 44.06,49.12 44.35,49.12 44.64,48.83 44.64,48.55 43.38,47.28 43.38,47 43.66,46.71 43.95,46.71 45.21,47.97 45.5,47.97 45.79,47.68 45.79,47.4 44.53,46.13 44.53,45.85 44.81,45.56 45.1,45.56 46.36,46.82 46.65,46.82 46.94,46.53 46.94,46.22 45.83,45.11 45.83,44.8 46.09,44.54 46.4,44.54 47.52,45.66 47.81,45.66 48.56,44.91 48.56,30.2 46.62,28.26 R26.2
  BOTTOM w0.203: v5(21.78,62.81) P1.48
TAL3: length 83.5
  TOP w0.203: v5(23.78,67.59) 19.91,63.72 19.91,61.11 21.72,59.31 30.63,59.31 32.31,57.63 32.31,56.96 32.51,56.75 33.35,56.75 33.58,56.52 33.58,56.17 33.35,55.94 32.51,55.94 32.31,55.74 32.31,55.36 32.56,55.1 34.98,55.1 35.18,54.9 35.18,54.49 34.98,54.29 32.51,54.29 32.31,54.09 32.31,53.71 32.56,53.45 36.02,53.45 36.22,53.25 36.22,52.84 36.02,52.64 32.51,52.64 32.31,52.44 32.31,52.08 32.56,51.83 36.02,51.83 36.22,51.62 36.22,51.22 36.02,51.01 32.51,51.01 32.31,50.81 32.31,50.45 32.56,50.2 36.02,50.2 36.22,50 36.22,49.59 36.02,49.39 32.51,49.39 32.31,49.18 32.31,48.83 32.56,48.57 36.02,48.57 36.22,48.37 36.22,47.97 36.02,47.76 32.54,47.76 32.33,47.56 32.33,47.18 32.56,46.95 35.74,46.95 35.94,46.75 35.94,46.34 35.74,46.14 32.51,46.14 32.31,45.93 32.31,45.31 31,44 R3.2
  BOTTOM w0.203: P1.40 v5(23.78,67.59)
TAL4: length 83.5
  TOP w0.203: R29.2 24.61,21.63 25.35,22.38 29.16,22.38 29.85,23.06 45.44,23.06 50.83,28.45 50.83,46.3 32.26,64.87 28.5,64.87 v5(25.79,67.59)
  BOTTOM w0.203: P1.32 v5(25.79,67.59)
UNNAMED_4_ADP250X_I213_FB: length 2.6
  TOP w0.203: R35.2 R37.1 39.22,70.63 39.57,70.98 U5.10
UNNAMED_4_ADP250X_I213_SW1: length 3
  TOP w0.203: U5.4 43.88,72.97 44.58,73.67 L1.1
UNNAMED_4_ADP250X_I213_SW2: length 3
  TOP w0.203: L1.2 44.58,71.26 43.88,71.97 U5.2
VLD_BRD: length 34.9
  TOP w0.508: v1(38.76,62.07) C18.2 R22.1 D8.C
  BOTTOM w0.254: 28.79,67.79 P1.20 28.79,70.05 ; 30.29,67.79 P1.14 30.29,70.05 ; 30.79,67.79 P1.12 30.79,70.05 ; P1.2 33.85,68.92 ; P1.2 33.29,67.79 ; P1.2 33.29,70.05 ; 32.29,67.79 P1.6 32.29,70.05 ; 32.79,70.05 P1.4 32.79,67.79 ; 28.29,67.79 P1.22 28.29,70.05 ; 27.79,70.05 P1.24 27.79,67.79 ; 29.29,67.79 P1.18 29.29,70.05 ; 31.79,67.79 P1.8 31.79,70.05 ; 31.29,70.05 P1.10 31.29,67.79 ; 29.79,70.05 P1.16 29.79,67.79
  vias: v1(29.06,67.18) v1(30.05,67.21) v1(31.06,67.21) v1(32.05,67.21) v1(33.07,67.21) v1(34.06,67.21)
VOUT: length 9.3
  TOP w0.203: U5.1 C26.2
  TOP w0.508: R37.2 39.22,68.38 39.73,67.87 42.3,67.87 42.68,68.25 C26.2 R39.1

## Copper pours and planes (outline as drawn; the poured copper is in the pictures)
5V_LD on L3_PWR: 0.51,77.47 22.39,77.47 22.39,69.24 22.41,69.12 22.48,69.02 23.4,68.1 23.5,68.03 23.62,68.01 52.07,68.01 52.07,0.51 0.51,0.51 ; 1 cut-out
5VDD_CON on BOTTOM: 23.85,76.96 26.72,76.96 26.95,76.73 26.95,75.84 23.62,75.84 23.62,76.73
5VDD_CON on L3_PWR: 23.03,77.47 52.07,77.47 52.07,68.64 23.75,68.64 23.03,69.37
AGND on TOP: 0.51,77.47 52.07,77.47 52.07,0.51 0.51,0.51 ; 16 cut-outs
AGND on BOTTOM: 0.51,77.47 52.07,77.47 52.07,0.51 0.51,0.51 ; 5 cut-outs
AGND on L2_GND: 52.07,77.47 0.51,77.47 0.51,0.51 52.07,0.51
AGND on L5_GND: 52.07,77.47 0.51,77.47 0.51,0.51 52.07,0.51
VIN on TOP: 43.89,76.58 40.13,76.58 39.24,75.69 39.24,74.85 38.73,74.35 37.97,74.35 37.31,73.69 37.31,72.42 37.41,72.31 40.01,72.31 40.01,75.41 40.49,75.9 41.91,75.9 42.21,75.59 42.21,74.6 43.15,74.6 43.15,74.96 44.22,74.96 44.22,76.25
3P3VDD on L4_PWR: 0.51,77.47 31.94,77.47 31.94,74.68 31.24,73.98 27.69,73.98 27.56,73.95 27.46,73.88 26.7,73.12 26.63,73.02 26.61,72.9 26.61,65.54 26.16,65.09 13.59,65.09 13.47,65.06 13.36,64.99 12.35,63.98 12.28,63.88 12.26,63.75 12.26,51.19 10.66,49.59 0.51,49.59
CATHODE1 on TOP: 5.99,32.54 5.99,33.88 7.34,35.23 9.25,35.23 9.5,35.48 9.5,36.96 9.7,37.16 10.92,37.16 11.07,37.01 11.07,35.43 11.28,35.23 14.02,35.23 14.38,34.87 14.38,32.56 14.1,32.28 6.25,32.28
CATHODE2 on TOP: 46.79,31.72 46.79,30.3 45.52,29.03 43.61,29.03 43.36,28.78 43.36,27.25 43.18,27.08 41.96,27.08 41.78,27.25 41.78,28.83 41.58,29.03 38.84,29.03 38.48,29.39 38.48,31.67 38.79,31.98 46.53,31.98
CATHODE3 on TOP: 31.06,47.5 31.06,46.05 29.79,44.78 27.89,44.78 27.64,44.53 27.64,43 27.46,42.82 26.24,42.82 26.06,43 26.06,44.58 25.86,44.78 23.11,44.78 22.76,45.14 22.76,47.45 23.04,47.73 30.84,47.73
CATHODE4 on TOP: 21.77,16.69 21.77,18.16 23.09,19.48 24.99,19.48 25.25,19.74 25.25,21.26 25.43,21.44 26.64,21.44 26.82,21.26 26.82,19.69 27.03,19.48 29.77,19.48 30.12,19.13 30.12,16.81 29.85,16.54 21.92,16.54
DS1 on TOP: 14.2,27.28 14.2,31.8 14.02,31.98 6.25,31.98 5.99,31.72 5.99,23.7 7.14,22.56 9.47,22.56 9.7,22.78 9.7,25.04 10.59,25.93 12.85,25.93
DS1 on BOTTOM: 10.54,24.66 10.54,31.67 9.7,32.51 7.01,32.51 6.02,31.52 6.02,24.77 6.68,24.1 9.98,24.1
DS2 on TOP: 38.61,36.96 38.61,32.46 38.79,32.28 46.53,32.28 46.79,32.54 46.79,40.59 45.69,41.68 43.31,41.68 43.1,41.48 43.1,39.19 42.24,38.33 39.98,38.33
DS2 on BOTTOM: 42.27,39.55 42.27,32.54 43.1,31.7 45.8,31.7 46.79,32.69 46.79,39.45 46.13,40.11 42.82,40.11
DS3 on TOP: 22.89,52.73 22.89,48.23 23.06,48.06 30.84,48.06 31.06,48.29 31.06,56.36 30,57.43 27.58,57.43 27.38,57.23 27.38,54.91 26.54,54.08 24.23,54.08
DS3 on BOTTOM: 26.54,55.3 26.54,48.29 27.38,47.45 30.07,47.45 31.06,48.44 31.06,55.19 30.4,55.85 27.1,55.85
DS4 on TOP: 30,11.53 30,16.05 29.82,16.23 21.92,16.23 21.77,16.08 21.77,7.98 22.89,6.86 25.3,6.86 25.5,7.06 25.5,9.37 26.34,10.21 28.68,10.21
DS4 on BOTTOM: 26.29,8.97 26.29,15.98 25.45,16.81 22.76,16.81 21.77,15.82 21.77,9.07 22.43,8.41 25.73,8.41
LD_SUPPLY on TOP: 40.79,41.68 40.46,41.35 40.46,38.96 40.84,38.58 42.14,38.58 42.85,39.29 42.85,41.48 42.65,41.68
LD_SUPPLY on TOP: 25.07,57.43 24.74,57.1 24.74,54.71 25.12,54.33 26.42,54.33 27.13,55.04 27.13,57.23 26.92,57.43
LD_SUPPLY on TOP: 27.84,6.86 28.17,7.19 28.17,9.58 27.79,9.96 26.49,9.96 25.78,9.25 25.78,7.06 25.98,6.86
LD_SUPPLY on TOP: 12.04,22.58 12.37,22.91 12.37,25.3 11.99,25.68 10.69,25.68 9.98,24.97 9.98,22.78 10.19,22.58
LD_SUPPLY on L4_PWR: 13.72,64.45 32.25,64.45 32.96,63.75 32.96,60.71 32.98,60.58 33.05,60.48 33.68,59.85 33.79,59.78 33.91,59.75 41.27,59.75 41.4,59.78 41.5,59.85 42.01,60.35 42.08,60.46 42.1,60.58 42.1,63.88 42.42,64.2 52.07,64.2 52.07,0.51 0.51,0.51 0.51,48.96 10.8,48.96 10.92,48.98 11.02,49.05 12.8,50.83 12.87,50.93 12.89,51.05 12.89,63.62 ; 1 cut-out
VLD_BRD on BOTTOM: 27.43,70.13 27.43,66.9 27.79,66.55 34.37,66.55 34.72,66.9 34.72,70.1 34.49,70.33 27.64,70.33
VLD_BRD on L4_PWR: 32.58,77.47 52.07,77.47 52.07,64.83 42.29,64.83 42.17,64.81 42.07,64.74 41.56,64.23 41.49,64.13 41.47,64.01 41.47,60.71 41.14,60.39 34.04,60.39 33.59,60.84 33.59,63.88 33.57,64 33.5,64.11 32.61,64.99 32.51,65.06 32.38,65.09 27.69,65.09 27.24,65.54 27.24,72.77 27.82,73.34 31.37,73.34 31.49,73.37 31.59,73.44 32.48,74.32 32.55,74.43 32.58,74.55 ; 1 cut-out

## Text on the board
Ref Des/Silkscreen Bottom: 08-051355 REV D Z | SECONDARY SIDE
User.Comments: SEE DETAIL A | 4 PLACES | 4.    ASSEMBLED BOARDS TO BE SHIPPED SINGULATED.
Ref Des/Assembly Top: A | C
Ref Des/Silkscreen Top: C | A | PRIMARY SIDE | 08-051355 REV D Z | 96ToF LASER1 | 987126A
PAGE_OUTLINE: 06NOV18 | B | C | D | AS PER ECR-085793 | AS PER ECR-088821 | AS PER ECR-094505 | 27MAR19 | 27JUN19 | 25MAY20 | MBANCISO | M. SUCIU | CUSTOMER EVAL Z
DIMENSION: (REF) | DIA MAX | SEE NOTE 16
DISPLAY_BOTTOM: 08-      -11
User.12: 50 OHMS | 15.    BOARDS TO BE SHIPPED IN ARRAYS | 16.    VIAS TO BE FILLED WITH NON-CONDUCTIVE EPOXY AND PLANARIZED ON PRIMARY SIDE.
User.45: FIGURE | SIZE | 5.0 | 8.0 | 12.0 | 16.0 | 65.0 | 40.0 | 120.0 | PLATED | NON-PLATED | FINISHED HOLES IN MILS | ALL UNITS ARE IN MILS | QTY | 28 | 13 | 17 | 688 | 2 | TOLERANCE/NOTES
